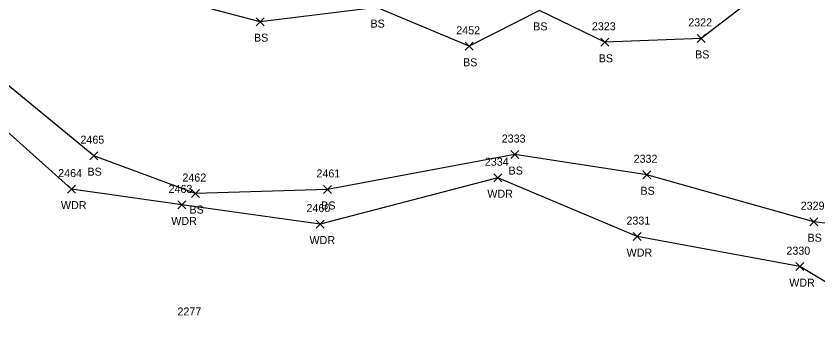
# Model space of a CAD drawing. Extents: x 1599569 to 1610055, y 642560 to 647860.
# Drawn here: x 1601302.9 to 1601503.2, y 647053 to 647129.7 of the extents above; entities that cross this region are included whole.
import ezdxf

# ---------------------------------------------------------------- set-up
doc = ezdxf.new("R2010")
doc.units = 0
for name, color, linetype in [('L_A', 7, 'Continuous'), ('L_I', 7, 'Continuous'), ('L_TIC', 7, 'Continuous'), ('LAWA', 7, 'Continuous'), ('LELB', 7, 'Continuous')]:
    doc.layers.add(name, color=color, linetype=linetype)

msp = doc.modelspace()

# ---------------------------------------------------------------- linework, layer by layer
at = {"layer": 'L_TIC'}
for points in [[(1601362.94, 647127.32), (1601364.94, 647129.32)], [(1601364.94, 647127.32), (1601362.94, 647129.32)], [(1601473.1, 647123.14), (1601475.1, 647125.14)], [(1601475.1, 647123.14), (1601473.1, 647125.14)], [(1601415.15, 647121.17), (1601417.15, 647123.17)], [(1601417.15, 647121.17), (1601415.15, 647123.17)], [(1601449.02, 647122.17), (1601451.02, 647124.17)], [(1601451.02, 647122.17), (1601449.02, 647124.17)], [(1601321.34, 647093.84), (1601323.34, 647095.84)], [(1601323.34, 647093.84), (1601321.34, 647095.84)], [(1601426.5, 647094.12), (1601428.5, 647096.12)], [(1601428.5, 647094.12), (1601426.5, 647096.12)], [(1601459.45, 647089.07), (1601461.45, 647091.07)], [(1601461.45, 647089.07), (1601459.45, 647091.07)], [(1601422.29, 647088.33), (1601424.29, 647090.33)], [(1601424.29, 647088.33), (1601422.29, 647090.33)], [(1601315.79, 647085.48), (1601317.79, 647087.48)], [(1601317.79, 647085.48), (1601315.79, 647087.48)], [(1601346.8, 647084.38), (1601348.8, 647086.38)], [(1601348.8, 647084.38), (1601346.8, 647086.38)], [(1601379.72, 647085.4), (1601381.72, 647087.4)], [(1601381.72, 647085.4), (1601379.72, 647087.4)], [(1601343.35, 647081.53), (1601345.35, 647083.53)], [(1601345.35, 647081.53), (1601343.35, 647083.53)], [(1601377.88, 647076.75), (1601379.88, 647078.75)], [(1601379.88, 647076.75), (1601377.88, 647078.75)], [(1601501.18, 647077.34), (1601503.18, 647079.34)], [(1601503.18, 647077.34), (1601501.18, 647079.34)], [(1601457.08, 647073.62), (1601459.08, 647075.62)], [(1601459.08, 647073.62), (1601457.08, 647075.62)], [(1601497.69, 647066.11), (1601499.69, 647068.11)], [(1601499.69, 647066.11), (1601497.69, 647068.11)]]:
    msp.add_lwpolyline(points, dxfattribs=at)
at = {"layer": 'LAWA'}
msp.add_lwpolyline([(1601543.96, 647141.4), (1601538.73, 647126.26), (1601544.78, 647095.79), (1601557.99, 647089.73), (1601552.59, 647056.78), (1601538.08, 647043.46), (1601498.69, 647067.11), (1601458.08, 647074.62), (1601423.29, 647089.33), (1601378.88, 647077.75), (1601344.35, 647082.53), (1601316.79, 647086.48), (1601287.75, 647112.48), (1601260.28, 647136.03), (1601236.79, 647176.35), (1601203.76, 647168.14), (1601147.97, 647142.06), (1601096.93, 647153.87), (1601082.37, 647126.05)], dxfattribs=at)
at = {"layer": 'LELB'}
for points in [[(1601751.67, 647030.89), (1601730.47, 647037.42), (1601697.62, 647051.94), (1601683.46, 647052.81), (1601660.42, 647063.53), (1601634.93, 647067.43), (1601609.86, 647081.03), (1601579.64, 647095.5), (1601544.78, 647095.79), (1601527.55, 647075.32), (1601502.18, 647078.34), (1601460.45, 647090.07), (1601427.5, 647095.12), (1601380.72, 647086.4), (1601347.8, 647085.38), (1601322.34, 647094.84), (1601293.67, 647118.34), (1601268.03, 647147.72), (1601257.75, 647175.7)], [(1601786.42, 647020.74), (1601762.67, 647028.99), (1601751.67, 647030.89), (1601732.96, 647040.23), (1601698.47, 647053.93), (1601685.61, 647056.76), (1601664.03, 647070.39), (1601639.36, 647075.33), (1601612.31, 647092.93), (1601584.19, 647104.61), (1601538.73, 647126.26), (1601520.13, 647131.26), (1601491.52, 647137.58), (1601474.1, 647124.14), (1601450.02, 647123.17), (1601433.67, 647131.14), (1601416.15, 647122.17), (1601393.03, 647131.84), (1601363.94, 647128.32), (1601336.7, 647135.49), (1601311.97, 647149.61), (1601287.9, 647169.52)]]:
    msp.add_lwpolyline(points, dxfattribs=at)

# ---------------------------------------------------------------- texts
at = {"layer": 'L_A'}
for s, p in [('BS', (1601391.47, 647126.84)), ('BS', (1601432.11, 647126.14)), ('BS', (1601362.38, 647123.32)), ('BS', (1601472.54, 647119.14)), ('BS', (1601414.59, 647117.17)), ('BS', (1601448.46, 647118.17)), ('BS', (1601320.78, 647089.84)), ('BS', (1601425.95, 647090.12)), ('BS', (1601458.89, 647085.07)), ('WDR', (1601420.65, 647084.33)), ('WDR', (1601314.15, 647081.48)), ('BS', (1601346.25, 647080.38)), ('BS', (1601379.16, 647081.4)), ('WDR', (1601341.71, 647077.53)), ('WDR', (1601376.24, 647072.75)), ('BS', (1601500.62, 647073.34)), ('WDR', (1601455.44, 647069.62)), ('WDR', (1601496.05, 647062.11))]:
    msp.add_text(s, height=2, dxfattribs=at).set_placement(p)
at = {"layer": 'L_I'}
for s, p in [('2322', (1601470.84, 647127.14)), ('2452', (1601412.89, 647125.17)), ('2323', (1601446.76, 647126.17)), ('2465', (1601319.03, 647097.84)), ('2333', (1601424.25, 647098.12)), ('2332', (1601457.19, 647093.07)), ('2334', (1601420.03, 647092.33)), ('2464', (1601313.48, 647089.48)), ('2462', (1601344.5, 647088.38)), ('2461', (1601377.98, 647089.4)), ('2463', (1601341.04, 647085.53)), ('2460', (1601375.48, 647080.75)), ('2329', (1601498.92, 647081.34)), ('2331', (1601455.39, 647077.62)), ('2330', (1601495.35, 647070.11)), ('2277', (1601343.26, 647054.91))]:
    msp.add_text(s, height=2, dxfattribs=at).set_placement(p)

doc.saveas('drawing.dxf')
